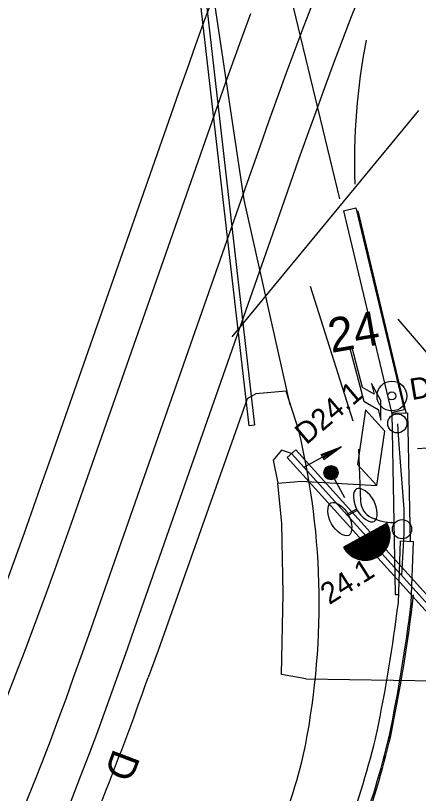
# Model space of a CAD drawing. Extents: x 81617 to 82144, y 454649 to 455150.
# Drawn here: x 81836.93 to 81851.04, y 454865.61 to 454892.85 of the extents above; entities that cross this region are included whole.
import ezdxf

# ---------------------------------------------------------------- set-up
doc = ezdxf.new("R2010")
doc.units = 0
for name, color, linetype in [('B-WE-OG-TOPOGRAFIE-G', 7, 'Continuous'), ('B-WE-VW-MARKERING-G', 7, 'Continuous'), ('N-OI-KL-VRI_KABEL_DETECTIE-G', 7, 'Continuous'), ('N-OI-KL-VRI_KABELGEUL-G', 7, 'Continuous'), ('N-OI-KL-VRI_LUS_DETECTIE-G', 7, 'Continuous'), ('N-OI-KL-VRI_LUS_DETECTIE-T18', 7, 'Continuous'), ('N-OI-KL-VRI_MANTELBUIS-G', 7, 'Continuous'), ('N-WE-VW-VRI_ARMATUUR-S', 7, 'Continuous'), ('N-WE-VW-VRI_ARMATUUR-T18', 7, 'Continuous'), ('N-WE-VW-VRI_MAST-S', 7, 'Continuous'), ('N-WE-VW-VRI_RICHTINGNUMMER-T25', 7, 'Continuous')]:
    doc.layers.add(name, color=color, linetype=linetype)

msp = doc.modelspace()

# ---------------------------------------------------------------- linework, layer by layer
at = {"layer": 'B-WE-OG-TOPOGRAFIE-G'}
for p, q in [((81848.417, 454886.012), (81848.854, 454886.116)), ((81848.417, 454886.012), (81850.103, 454878.956)), ((81848.854, 454886.116), (81850.54, 454879.061)), ((81846.405, 454879.702), (81845.349, 454879.599)), ((81846.852, 454878.323), (81846.405, 454879.702)), ((81850.103, 454878.956), (81850.54, 454879.061)), ((81850.108, 454878.925), (81850.663, 454878.936)), ((81850.108, 454878.925), (81850.233, 454872.572)), ((81850.663, 454878.936), (81850.752, 454874.443)), ((81850.34, 454872.297), (81850.417, 454874.455)), ((81850.417, 454874.455), (81850.867, 454874.439)), ((81850.789, 454872.261), (81850.867, 454874.439)), ((81850.233, 454872.572), (81850.35, 454872.572))]:
    msp.add_line(p, q, dxfattribs=at)
msp.add_lwpolyline([(81845.114, 454878.488), (81843.298, 454894.349), (81843.487, 454894.37), (81845.303, 454878.51)], close=True, dxfattribs=at)
for points in [[(81849.019, 454893.625), (81848.691, 454892.804), (81848.371, 454891.979), (81848.057, 454891.15), (81847.748, 454890.319), (81847.445, 454889.485), (81847.145, 454888.648), (81846.847, 454887.81), (81846.257, 454886.13)], [(81836.664, 454873.121), (81836.956, 454873.931), (81837.246, 454874.742), (81837.82, 454876.369), (81838.105, 454877.184), (81842.379, 454889.381), (81842.664, 454890.19), (81842.95, 454890.998), (81843.239, 454891.807), (81843.531, 454892.615), (81843.827, 454893.422)], [(81847.356, 454893.33), (81847.031, 454892.493), (81846.713, 454891.654), (81846.401, 454890.814), (81846.095, 454889.972), (81845.794, 454889.13), (81845.494, 454888.288), (81844.903, 454886.605)], [(81839.46, 454876.71), (81843.733, 454888.906), (81844.017, 454889.713), (81844.302, 454890.518), (81844.589, 454891.322), (81844.879, 454892.124), (81845.173, 454892.924)], [(81844.903, 454886.604), (81839.743, 454871.882), (81839.482, 454871.138), (81839.219, 454870.396), (81838.954, 454869.656), (81838.687, 454868.917), (81838.416, 454868.18), (81838.141, 454867.445), (81837.861, 454866.713), (81837.575, 454865.984), (81837.282, 454865.256), (81837.135, 454864.898), (81836.833, 454864.175)], [(81846.257, 454886.129), (81841.097, 454871.407), (81840.835, 454870.661), (81840.571, 454869.915), (81840.304, 454869.17), (81840.035, 454868.425), (81839.761, 454867.681), (81839.483, 454866.937), (81839.199, 454866.195), (81838.909, 454865.455), (81838.612, 454864.716), (81838.461, 454864.348), (81838.153, 454863.613), (81837.836, 454862.881), (81837.509, 454862.152), (81837.173, 454861.427), (81836.825, 454860.707)], [(81845.349, 454879.599), (81845.045, 454879.433)], [(81845.045, 454879.433), (81841.928, 454870.616), (81841.574, 454869.677)], [(81836.624, 454868.976), (81836.944, 454869.785), (81837.256, 454870.596), (81837.562, 454871.409), (81837.713, 454871.816), (81838.012, 454872.631), (81838.307, 454873.446), (81838.598, 454874.262), (81838.887, 454875.078), (81839.46, 454876.709)]]:
    msp.add_lwpolyline(points, dxfattribs=at)
for centre, radius, start, end in [((81821.612, 454872.276), 25.954, 348.1215, 13.4718), ((81793.939, 454879.284), 56.832, 348.2742, 352.9379), ((81793.939, 454879.284), 57.282, 348.2742, 352.9577), ((81744.949, 454903.377), 102.333, 335.38677, 340.77263), ((81821.582, 454874.325), 28.769, 331.9437, 346.7819), ((81821.582, 454874.325), 29.219, 331.9437, 346.7819), ((81824.821, 454872.343), 22.839, 328.39, 346.2989)]:
    msp.add_arc(centre, radius, start, end, dxfattribs=at)
at = {"layer": 'B-WE-VW-MARKERING-G'}
for p, q in [((81848.296, 454886.436), (81845.716, 454897.06)), ((81851.044, 454889.524), (81844.504, 454881.602)), ((81848.417, 454886.012), (81850.103, 454878.956)), ((81848.92, 454886.012), (81850.606, 454878.956)), ((81848.762, 454878.649), (81847.262, 454883.365)), ((81856.964, 454874.469), (81850.333, 454882.22)), ((81848.71, 454881.26), (81848.63, 454881.239)), ((81848.63, 454881.239), (81849.13, 454879.352)), ((81849.09, 454879.825), (81848.71, 454881.26)), ((81849.723, 454879.367), (81849.395, 454879.962)), ((81849.395, 454879.962), (81849.493, 454879.59)), ((81849.493, 454879.59), (81849.09, 454879.825)), ((81849.13, 454879.352), (81849.634, 454879.059)), ((81849.732, 454878.686), (81849.723, 454879.367)), ((81849.634, 454879.059), (81849.732, 454878.686)), ((81851.016, 454877.689), (81856.772, 454878.062)), ((81848.948, 454877.67), (81849.018, 454875.844))]:
    msp.add_line(p, q, dxfattribs=at)
msp.add_lwpolyline([(81843.676, 454894.754), (81844.933, 454886.403), (81846.535, 454879.217)], dxfattribs=at)
for centre, radius, start, end in [((81871.183, 454887.744), 22.379, 169.0756, 182.0506), ((81849.677, 454875.872), 0.66, 182.4438, 243.8095), ((81850.176, 454876.907), 1.809, 244.0982, 269.7501), ((81793.939, 454879.284), 57.332, 348.27422, 353.2675), ((81821.582, 454874.325), 29.269, 331.9437, 346.7819)]:
    msp.add_arc(centre, radius, start, end, dxfattribs=at)
at = {"layer": 'N-OI-KL-VRI_KABEL_DETECTIE-G'}
for p, q in [((81846.915, 454876.549), (81849.586, 454876.395)), ((81847.104, 454869.626), (81852.875, 454869.531))]:
    msp.add_line(p, q, dxfattribs=at)
at = {"layer": 'N-OI-KL-VRI_KABELGEUL-G'}
for points in [[(81850.46, 454873.24), (81850.545, 454874.709), (81850.54, 454875.567), (81850.362, 454877.979), (81850.322, 454878.552)], [(81862.44, 454851.616), (81862.582, 454852.027), (81862.754, 454852.346), (81865.008, 454854.754), (81865.955, 454855.815), (81865.903, 454856.153), (81846.599, 454877.513), (81846.252, 454877.634), (81845.96, 454877.281), (81846.114, 454876.473)], [(81847.104, 454869.626), (81846.241, 454869.773), (81846.306, 454872.602), (81846.255, 454875.064), (81846.114, 454876.473), (81846.687, 454876.524), (81846.915, 454876.549)]]:
    msp.add_lwpolyline(points, dxfattribs=at)
at = {"layer": 'N-OI-KL-VRI_LUS_DETECTIE-G'}
for p, q in [((81849.195, 454879.04), (81848.91, 454877.133)), ((81849.87, 454878.302), (81849.195, 454879.04)), ((81849.586, 454876.395), (81849.87, 454878.302)), ((81848.91, 454877.133), (81849.586, 454876.395))]:
    msp.add_line(p, q, dxfattribs=at)
at = {"layer": 'N-OI-KL-VRI_MANTELBUIS-G'}
msp.add_lwpolyline([(81866.052, 454856.287), (81865.755, 454856.019), (81846.451, 454877.379), (81846.747, 454877.647)], close=True, dxfattribs=at)
at = {"layer": 'N-WE-VW-VRI_ARMATUUR-S'}
for p, q in [((81847.024, 454877.033), (81848.341, 454877.752)), ((81847.635, 454877.481), (81848.341, 454877.752)), ((81848.341, 454877.752), (81847.659, 454877.437)), ((81848.341, 454877.752), (81847.707, 454877.349)), ((81847.731, 454877.305), (81848.341, 454877.752)), ((81847.683, 454877.393), (81847.635, 454877.481)), ((81847.683, 454877.393), (81847.731, 454877.305))]:
    msp.add_line(p, q, dxfattribs=at)
for points in [[(81848.462, 454875.967), (81848.102, 454876.625)], [(81848.879, 454875.568), (81848.572, 454875.4)], [(81848.903, 454875.524), (81848.596, 454875.356)], [(81849.949, 454875.07), (81848.413, 454874.231)], [(81848.428, 454874.205), (81849.963, 454875.043)], [(81848.443, 454874.179), (81849.976, 454875.016)], [(81848.46, 454874.154), (81849.988, 454874.989)], [(81848.478, 454874.13), (81849.999, 454874.961)], [(81848.496, 454874.105), (81850.009, 454874.932)], [(81848.516, 454874.082), (81850.019, 454874.903)], [(81848.536, 454874.059), (81850.027, 454874.873)], [(81848.557, 454874.036), (81850.034, 454874.843)], [(81848.58, 454874.014), (81850.041, 454874.812)], [(81848.603, 454873.993), (81850.046, 454874.781)], [(81848.628, 454873.972), (81850.05, 454874.749)], [(81848.654, 454873.952), (81850.053, 454874.717)], [(81848.68, 454873.933), (81850.055, 454874.684)], [(81848.709, 454873.914), (81850.056, 454874.65)], [(81848.738, 454873.896), (81850.055, 454874.615)], [(81848.769, 454873.878), (81850.053, 454874.58)], [(81848.801, 454873.862), (81850.049, 454874.544)], [(81848.835, 454873.846), (81850.044, 454874.507)], [(81848.871, 454873.832), (81850.037, 454874.468)], [(81848.91, 454873.819), (81850.027, 454874.429)], [(81848.95, 454873.806), (81850.016, 454874.389)], [(81848.993, 454873.796), (81850.001, 454874.347)], [(81849.039, 454873.787), (81849.984, 454874.303)], [(81849.09, 454873.78), (81849.962, 454874.257)], [(81849.145, 454873.776), (81849.936, 454874.208)], [(81849.207, 454873.776), (81849.903, 454874.156)], [(81849.279, 454873.781), (81849.86, 454874.098)], [(81849.369, 454873.796), (81849.799, 454874.031)]]:
    msp.add_lwpolyline(points, dxfattribs=at)
for points in [[(81849.496, 454875.136), (81849.544, 454875.179), (81849.577, 454875.244), (81849.596, 454875.327), (81849.6, 454875.424), (81849.591, 454875.531), (81849.567, 454875.643), (81849.529, 454875.757), (81849.478, 454875.867), (81849.413, 454875.969), (81849.338, 454876.062), (81849.257, 454876.143), (81849.172, 454876.209), (81849.088, 454876.257), (81849.007, 454876.287), (81848.934, 454876.294), (81848.873, 454876.277), (81848.825, 454876.234), (81848.792, 454876.169), (81848.773, 454876.086), (81848.768, 454875.988), (81848.778, 454875.881), (81848.802, 454875.769), (81848.839, 454875.656), (81848.891, 454875.546), (81848.956, 454875.443), (81849.031, 454875.35), (81849.112, 454875.27), (81849.197, 454875.204), (81849.281, 454875.155), (81849.361, 454875.126), (81849.434, 454875.119), (81849.496, 454875.136)], [(81848.602, 454874.648), (81848.54, 454874.63), (81848.467, 454874.638), (81848.387, 454874.667), (81848.303, 454874.716), (81848.218, 454874.781), (81848.137, 454874.862), (81848.062, 454874.955), (81847.997, 454875.058), (81847.945, 454875.168), (81847.908, 454875.281), (81847.884, 454875.393), (81847.874, 454875.5), (81847.879, 454875.597), (81847.898, 454875.681), (81847.931, 454875.746), (81847.979, 454875.788), (81848.04, 454875.805), (81848.113, 454875.798), (81848.194, 454875.769), (81848.278, 454875.72), (81848.363, 454875.655), (81848.444, 454875.574), (81848.519, 454875.481), (81848.584, 454875.378), (81848.635, 454875.268), (81848.673, 454875.155), (81848.697, 454875.043), (81848.706, 454874.936), (81848.702, 454874.839), (81848.683, 454874.755), (81848.65, 454874.69), (81848.602, 454874.648)]]:
    msp.add_lwpolyline(points, close=True, dxfattribs=at)
for centre, radius in [((81850.115, 454879.528), 0.522), ((81850.11, 454879.532), 0.141), ((81847.982, 454876.844), 0.25), ((81847.982, 454876.844), 0.225), ((81847.982, 454876.844), 0.2), ((81847.982, 454876.844), 0.175), ((81847.982, 454876.844), 0.15), ((81847.982, 454876.844), 0.125), ((81847.982, 454876.844), 0.1), ((81847.982, 454876.844), 0.075), ((81847.982, 454876.844), 0.05), ((81847.982, 454876.844), 0.025)]:
    msp.add_circle(centre, radius, dxfattribs=at)
msp.add_arc((81849.181, 454874.65), 0.875, 208.6474, 28.6474, dxfattribs=at)
at = {"layer": 'N-WE-VW-VRI_MAST-S'}
for centre in [(81850.304, 454878.57), (81850.469, 454874.864)]:
    msp.add_circle(centre, 0.335, dxfattribs=at)

# ---------------------------------------------------------------- texts
at = {"layer": 'B-WE-OG-TOPOGRAFIE-G'}
msp.add_text('D', height=1, rotation=249.2843, dxfattribs=at).set_placement((81840.374, 454867.212))
at = {"layer": 'N-OI-KL-VRI_LUS_DETECTIE-T18'}
msp.add_text('D24.1', height=0.75, rotation=40.2842, dxfattribs=at).set_placement((81847.118, 454877.797))
at = {"layer": 'N-WE-VW-VRI_ARMATUUR-T18'}
for s, rotation, p in [('DK24.1', 9.603, (81850.809, 454879.383)), ('24.1', 32.3566, (81847.918, 454872.2))]:
    msp.add_text(s, height=0.75, rotation=rotation, dxfattribs=at).set_placement(p)
at = {"layer": 'N-WE-VW-VRI_RICHTINGNUMMER-T25'}
msp.add_text('24', height=1.2, rotation=9.8783, dxfattribs=at).set_placement((81847.99, 454881.035))

doc.saveas('drawing.dxf')
